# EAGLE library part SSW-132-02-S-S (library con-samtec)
THROUGH-HOLE .025" SQ POST SOCKET Source: Samtec SSW.pdf
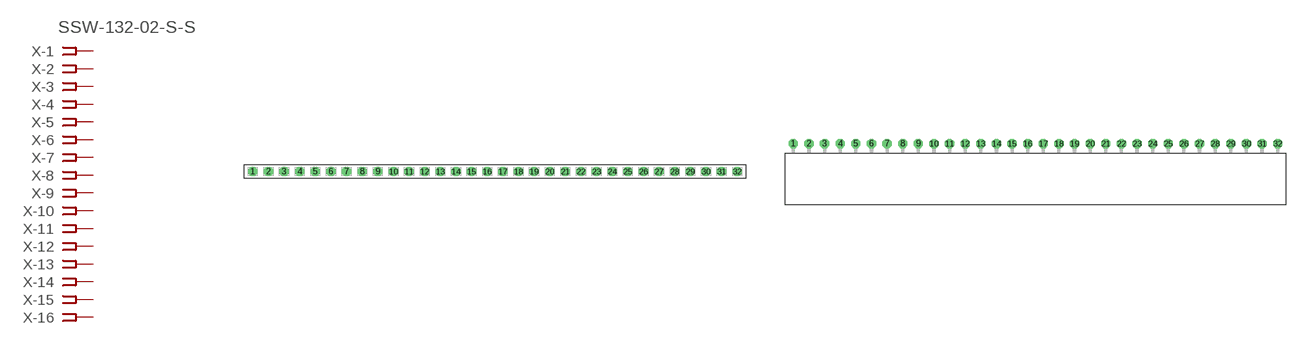
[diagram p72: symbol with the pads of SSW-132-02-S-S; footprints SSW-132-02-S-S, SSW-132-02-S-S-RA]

Designator prefix X; gates -1=FPINV -2=FPIN -3=FPIN -4=FPIN -5=FPIN -6=FPIN -7=FPIN -8=FPIN -9=FPIN -10=FPIN -11=FPIN -12=FPIN -13=FPIN -14=FPIN -15=FPIN -16=FPIN -17=FPIN -18=FPIN -19=FPIN -20=FPIN -21=FPIN -22=FPIN -23=FPIN -24=FPIN -25=FPIN -26=FPIN -27=FPIN -28=FPIN -29=FPIN -30=FPIN -31=FPIN -32=FPIN

## SSW-132-02-S-S (MPN: SSW-132-02-S-S; OC_FARNELL: unknown; OC_NEWARK: 11P9839)  [SSW-132-02-S-S]
1  -1:1  pas
2  -2:1  pas
3  -3:1  pas
4  -4:1  pas
5  -5:1  pas
6  -6:1  pas
7  -7:1  pas
8  -8:1  pas
9  -9:1  pas
10  -10:1  pas
11  -11:1  pas
12  -12:1  pas
13  -13:1  pas
14  -14:1  pas
15  -15:1  pas
16  -16:1  pas
17  -17:1  pas
18  -18:1  pas
19  -19:1  pas
20  -20:1  pas
21  -21:1  pas
22  -22:1  pas
23  -23:1  pas
24  -24:1  pas
25  -25:1  pas
26  -26:1  pas
27  -27:1  pas
28  -28:1  pas
29  -29:1  pas
30  -30:1  pas
31  -31:1  pas
32  -32:1  pas

## SSW-132-02-S-S-RA (MPN: SSW-132-02-S-S-RA; OC_FARNELL: unknown; OC_NEWARK: 11P9840)  [SSW-132-02-S-S-RA]
Pads as for SSW-132-02-S-S

## Footprint SSW-132-02-S-S (pad centres in mm)
THROUGH-HOLE .025" SQ POST SOCKET Source: Samtec SSW.pdf
drill 1 pad 1.5 octagon: 1 -39.37,0; 2 -36.83,0; 3 -34.29,0; 4 -31.75,0; 5 -29.21,0; 6 -26.67,0; 7 -24.13,0; 8 -21.59,0; 9 -19.05,0; 10 -16.51,0; 11 -13.97,0; 12 -11.43,0; 13 -8.89,0; 14 -6.35,0; 15 -3.81,0; 16 -1.27,0; 17 1.27,0; 18 3.81,0; 19 6.35,0; 20 8.89,0; 21 11.43,0; 22 13.97,0; 23 16.51,0; 24 19.05,0; 25 21.59,0; 26 24.13,0; 27 26.67,0; 28 29.21,0; 29 31.75,0; 30 34.29,0; 31 36.83,0; 32 39.37,0

## Footprint SSW-132-02-S-S-RA (pad centres in mm)
THROUGH-HOLE .025" SQ POST SOCKET Source: Samtec SSW.pdf
drill 1 pad 1.5 octagon: 1 -39.37,1.524; 2 -36.83,1.524; 3 -34.29,1.524; 4 -31.75,1.524; 5 -29.21,1.524; 6 -26.67,1.524; 7 -24.13,1.524; 8 -21.59,1.524; 9 -19.05,1.524; 10 -16.51,1.524; 11 -13.97,1.524; 12 -11.43,1.524; 13 -8.89,1.524; 14 -6.35,1.524; 15 -3.81,1.524; 16 -1.27,1.524; 17 1.27,1.524; 18 3.81,1.524; 19 6.35,1.524; 20 8.89,1.524; 21 11.43,1.524; 22 13.97,1.524; 23 16.51,1.524; 24 19.05,1.524; 25 21.59,1.524; 26 24.13,1.524; 27 26.67,1.524; 28 29.21,1.524; 29 31.75,1.524; 30 34.29,1.524; 31 36.83,1.524; 32 39.37,1.524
